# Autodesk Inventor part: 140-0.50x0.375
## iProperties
Created: 2007-07
Part Number: 140-0.50x0.375
Document SubType Name: Modeling
Designer: btaylor
Density: 1 g/cm^3
Author: btaylor
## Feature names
1. Extrusion1
2. Extrusion2
3. Chamfer1
4. Extrusion3
5. Chamfer2
6. Revolution1
7. Fillet1
8. Fillet2
